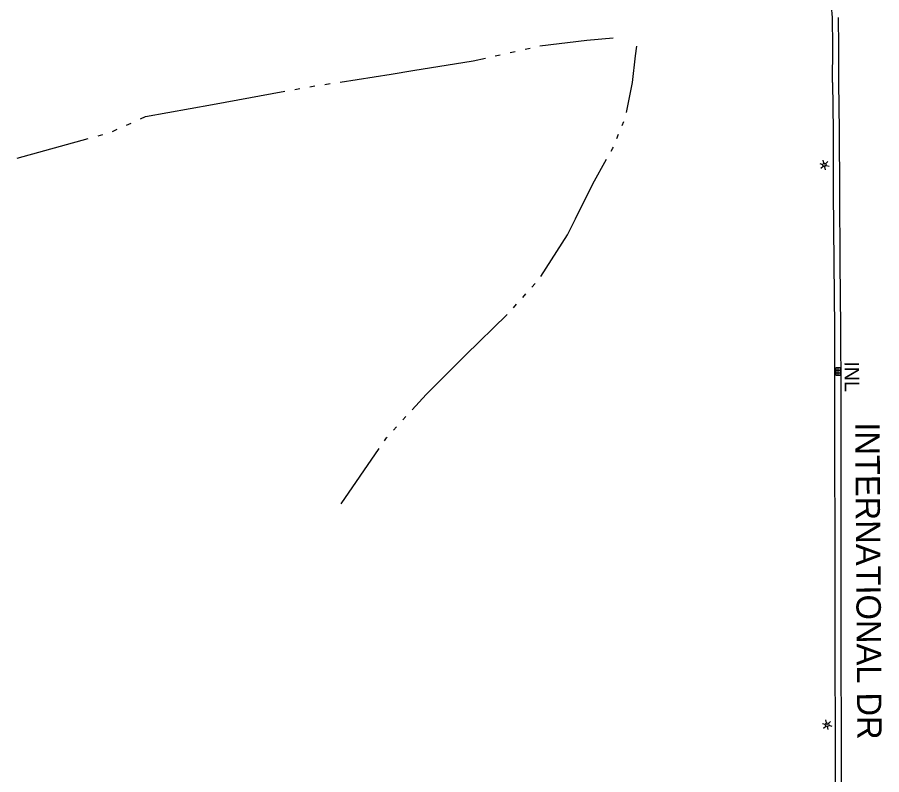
# Model space of a CAD drawing. Extents: x 588843 to 2552415, y 180129 to 269402.
# Drawn here: x 598872.5 to 599226.6, y 183375.6 to 183686 of the extents above; entities that cross this region are included whole.
import ezdxf

# ---------------------------------------------------------------- set-up
doc = ezdxf.new("R2010")
doc.units = 0
for name, color, linetype in [('E_DRN', 7, 'Continuous'), ('E_DRN_Text', 7, 'Continuous'), ('E_LTG', 7, 'Continuous'), ('E_RDWY_C_and_G', 7, 'Continuous'), ('E_RDWY_Text', 7, 'Continuous'), ('E_WTR_P', 7, 'Continuous')]:
    doc.layers.add(name, color=color, linetype=linetype)

# ---------------------------------------------------------------- blocks, each defined once
blk = doc.blocks.new('LPOL_4')
at = {"layer": 'E_LTG'}
for p, q in [((-13.1, 0), (-4.9, 0)), ((-2.5, 4.3), (-6.6, 11.4)), ((2.5, 4.3), (6.6, 11.4)), ((4.9, 0), (13.1, 0)), ((-6.6, -11.4), (-2.5, -4.3)), ((6.6, -11.4), (2.5, -4.3))]:
    blk.add_line(p, q, dxfattribs=at)
for radius in [4.92, 4.92, 4.92, 0.41]:
    blk.add_circle((0, 0), radius, dxfattribs=at)
blk = doc.blocks.new('INLO_3')
at = {"layer": 'E_DRN'}
for p, q in [((6.6, -13.1), (6.6, 0)), ((13.1, -13.1), (13.1, 0)), ((19.7, -6.6), (0, -6.6))]:
    blk.add_line(p, q, dxfattribs=at)
blk.add_lwpolyline([(0, -13.1), (19.7, -13.1), (19.7, 0), (0, 0)], close=True, dxfattribs=at)
blk = doc.blocks.new('INLT_10_1')
at = {"layer": 'E_DRN_Text'}
blk.add_text('INL', height=39.37, dxfattribs=at).set_placement((-36.2, -19.7))

msp = doc.modelspace()

# ---------------------------------------------------------------- linework, layer by layer
at = {"layer": 'E_RDWY_C_and_G'}
for points in [[(599192.3, 183728.81), (599197.88, 183720.8), (599200.69, 183715.4), (599203, 183710.46), (599204.38, 183706.01), (599205.08, 183699.94), (599206.23, 183685.85)], [(599206.23, 183685.85), (599206.39, 183673.85), (599206.33, 183659.25)], [(599208.73, 183685.88), (599208.89, 183673.86), (599208.83, 183659.24)], [(599206.43, 183659.25), (599206.67, 183639.42), (599206.72, 183614.12), (599206.96, 183585.46)], [(599208.93, 183659.28), (599209.17, 183639.43), (599209.22, 183614.13), (599209.46, 183585.48)], [(599206.96, 183585.46), (599207.2, 183558.61), (599207.29, 183531.59), (599207.3, 183503.96)], [(599209.46, 183585.48), (599209.7, 183558.62), (599209.79, 183531.6), (599209.8, 183503.96)], [(599207.3, 183503.96), (599207.32, 183474.51), (599207.37, 183446.65)], [(599209.8, 183503.96), (599209.82, 183474.51), (599209.87, 183446.65)], [(599207.37, 183446.65), (599207.4, 183422.42), (599207.52, 183392.94), (599207.46, 183361.38)], [(599209.87, 183446.65), (599209.9, 183422.43), (599210.02, 183392.95), (599209.96, 183361.38)]]:
    msp.add_lwpolyline(points, dxfattribs=at)
at = {"layer": 'E_WTR_P'}
for points in [[(599086.57, 183674.27), (599086.58, 183674.27), (599105.82, 183676.61), (599116.55, 183677.56)], [(599074.39, 183671.53), (599076.42, 183671.99)], [(599080.48, 183672.9), (599082.51, 183673.36)], [(599122.07, 183646.92), (599124.49, 183659.26), (599125.73, 183670.21), (599126.22, 183674.12)], [(599034.51, 183664.11), (599059.2, 183668.11), (599064.24, 183669.24)], [(599068.3, 183670.16), (599070.33, 183670.62)], [(599004.7, 183659.44), (599025.62, 183662.67), (599034.51, 183664.11)], [(598992.36, 183657.53), (598994.42, 183657.85)], [(598998.53, 183658.48), (599000.59, 183658.8)], [(598952.45, 183650.23), (598957.64, 183651.17), (598982.12, 183655.68)], [(598986.22, 183656.44), (598988.26, 183656.81)], [(598922.92, 183644.32), (598924.99, 183645.25), (598952.45, 183650.23)], [(599120.2, 183641.56), (599120.91, 183643.32)], [(598911.53, 183639.22), (598913.43, 183640.07)], [(598917.23, 183641.77), (598919.12, 183642.62)], [(598872.49, 183628.22), (598901.56, 183636.28)], [(598905.57, 183637.39), (598907.58, 183637.95)], [(599118.07, 183636.27), (599118.78, 183638.03)], [(599115.77, 183631.07), (599116.49, 183632.34), (599116.66, 183632.75)], [(599101.14, 183603.38), (599108.19, 183617.67), (599113.9, 183627.77)], [(599086.95, 183579.82), (599097.88, 183596.76), (599101.14, 183603.38)], [(599083.31, 183575.45), (599084.58, 183576.87)], [(599079.52, 183571.21), (599080.78, 183572.62)], [(599075.72, 183566.96), (599076.98, 183568.37)], [(599053.46, 183544.91), (599056.14, 183547.59), (599073.09, 183564.22)], [(599034.26, 183525.18), (599039.93, 183531.37), (599053.46, 183544.91)], [(599030.41, 183520.98), (599031.7, 183522.38)], [(599026.57, 183516.77), (599027.85, 183518.18)], [(599022.88, 183512.44), (599023.71, 183513.65), (599024, 183513.97)], [(599005.21, 183486.57), (599020.74, 183509.31)]]:
    msp.add_lwpolyline(points, dxfattribs=at)

# ---------------------------------------------------------------- block references
at = {"layer": 'E_DRN', "xscale": 0.1524003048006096, "yscale": 0.1524003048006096, "rotation": -89.83029807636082}
msp.add_blockref('INLO_3', (599209.75, 183542.32), dxfattribs=at)
at = {"layer": 'E_DRN_Text', "xscale": 0.1524003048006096, "yscale": 0.1524003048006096, "rotation": -89.83029807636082}
msp.add_blockref('INLT_10_1', (599214.35, 183539.45), dxfattribs=at)
at = {"layer": 'E_LTG', "xscale": 0.1524003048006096, "yscale": 0.1524003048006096, "rotation": -16.127348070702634}
for p in [(599203.09, 183625.47), (599204.19, 183396.1)]:
    msp.add_blockref('LPOL_4', p, dxfattribs=at)

# ---------------------------------------------------------------- texts
at = {"layer": 'E_RDWY_Text'}
msp.add_text('INTERNATIONAL DR', height=10, rotation=270.3944, dxfattribs=at).set_placement((599215.7, 183519.99))

doc.saveas('drawing.dxf')
